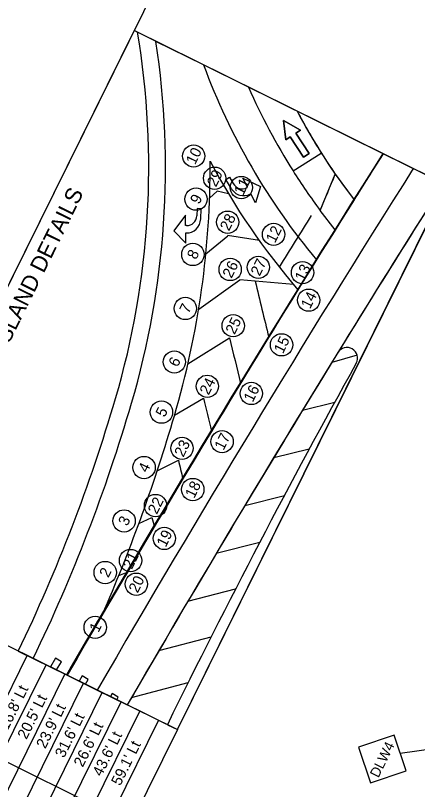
# Model space of a CAD drawing. Extents: x 14097936 to 14128734, y 8632000 to 8683104.
# Drawn here: x 14118361 to 14118650, y 8668139 to 8668694 of the extents above; entities that cross this region are included whole.
import ezdxf

# ---------------------------------------------------------------- set-up
doc = ezdxf.new("R2010")
doc.units = 0
for name, color, linetype in [('Cell', 7, 'Continuous'), ('dsn_stg_shd_prev', 7, 'Continuous'), ('dsnNonPlotable', 7, 'Continuous'), ('dsnPaintPlaceBrokenLaneWhite', 7, 'Continuous'), ('dsnPaintPlaceChannelizingLaneWhite', 7, 'Continuous'), ('dsnPaintPlaceChannelizingLaneYellow', 7, 'Continuous'), ('dsnPaintPlaceStopLineWhite', 7, 'Continuous'), ('dsnShadingPaved', 7, 'Continuous'), ('dsnStdLabel', 7, 'Continuous'), ('dsnStgShadingPrevPav', 7, 'Continuous'), ('dsnStgShadingPropPav', 7, 'Continuous'), ('Level 2', 7, 'Continuous'), ('Level 5', 7, 'Continuous')]:
    doc.layers.add(name, color=color, linetype=linetype)

msp = doc.modelspace()

# ---------------------------------------------------------------- linework, layer by layer
at = {"layer": 'Cell'}
for p, q in [((14118527.19, 8668570.77), (14118527.74, 8668571.09)), ((14118530.15, 8668566.41), (14118529.83, 8668566.23)), ((14118484, 8668543.49), (14118483.38, 8668543.51)), ((14118483.4, 8668538.25), (14118483.77, 8668538.23))]:
    msp.add_line(p, q, dxfattribs=at)
for points in [[(14118515.94, 8668570.32), (14118512.25, 8668576.69), (14118514.83, 8668578.19), (14118517.47, 8668573.64)], [(14118515.94, 8668570.32), (14118512.25, 8668576.69), (14118514.83, 8668578.19), (14118517.47, 8668573.64)], [(14118527.74, 8668571.09), (14118524.36, 8668577.64), (14118537.06, 8668571.63)], [(14118527.74, 8668571.09), (14118524.36, 8668577.64), (14118537.06, 8668571.63)], [(14118527.19, 8668570.77), (14118527.74, 8668571.09)], [(14118537.06, 8668571.63), (14118533.52, 8668559.86), (14118530.15, 8668566.41)], [(14118537.06, 8668571.63), (14118533.52, 8668559.86), (14118530.15, 8668566.41)], [(14118530.15, 8668566.41), (14118529.83, 8668566.23)], [(14118494.19, 8668548.29), (14118494.52, 8668555.65), (14118491.53, 8668555.78), (14118491.3, 8668550.53)], [(14118494.19, 8668548.29), (14118494.52, 8668555.65), (14118491.53, 8668555.78), (14118491.3, 8668550.53)], [(14118483.38, 8668543.51), (14118483.34, 8668550.88), (14118474.86, 8668539.68)], [(14118483.38, 8668543.51), (14118483.34, 8668550.88), (14118474.86, 8668539.68)], [(14118484, 8668543.49), (14118483.38, 8668543.51)], [(14118474.86, 8668539.68), (14118483.44, 8668530.88), (14118483.4, 8668538.25)], [(14118474.86, 8668539.68), (14118483.44, 8668530.88), (14118483.4, 8668538.25)], [(14118483.4, 8668538.25), (14118483.77, 8668538.23)]]:
    msp.add_lwpolyline(points, dxfattribs=at)
for centre, major_axis, start_param, end_param in [((14118523.5, 8668577.14), (-3.69, 6.37), 1.570796, 3.141593), ((14118523.5, 8668577.14), (-3.69, 6.37), 1.570796, 3.141593), ((14118524.56, 8668575.32), (-5.28, 9.09), 1.570796, 3.141593), ((14118524.56, 8668575.32), (-5.28, 9.09), 1.570796, 3.141593), ((14118484.24, 8668548.74), (0.47, 10.5), 3.141593, 4.712389), ((14118484.24, 8668548.74), (0.47, 10.5), 3.141593, 4.712389), ((14118484.33, 8668550.84), (0.33, 7.35), 3.141593, 4.712389), ((14118484.33, 8668550.84), (0.33, 7.35), 3.141593, 4.712389)]:
    msp.add_ellipse(centre, major_axis=major_axis, ratio=0.9474, start_param=start_param, end_param=end_param, dxfattribs=at)
at = {"layer": 'dsn_stg_shd_prev'}
for p, q in [((14118624.96, 8668595.1), (14118448.86, 8668682.17)), ((14118363.35, 8668238.29), (14118398.34, 8668220.99))]:
    msp.add_line(p, q, dxfattribs=at)
msp.add_lwpolyline([(14118398.34, 8668220.99), (14118477.41, 8668181.9), (14118670.56, 8668572.56), (14118624.96, 8668595.1)], dxfattribs=at)
for centre, radius, start, end in [((14117868.92, 8668585.15), 588, 343.63038, 9.49722), ((14127938.79, 8662697.56), 11024, 147.657875, 149.931333), ((14127938.79, 8662697.56), 11024, 147.657875, 149.931333), ((14117293.24, 8668754.25), 1188, 334.25871, 343.63038)]:
    msp.add_arc(centre, radius, start, end, dxfattribs=at)
at = {"layer": 'dsnNonPlotable'}
msp.add_lwpolyline([(14118047.21, 8667875.87), (14118741.94, 8669281.01), (14119647.32, 8668833.36), (14118952.59, 8667428.23)], close=True, dxfattribs=at)
at = {"layer": 'dsnPaintPlaceBrokenLaneWhite'}
msp.add_arc((14127939.53, 8662698.67), 11000, 147.651625, 149.930056, dxfattribs=at)
at = {"layer": 'dsnPaintPlaceChannelizingLaneWhite'}
for p, q in [((14118500.54, 8668563.17), (14118505.96, 8668568.25)), ((14118514.16, 8668566.21), (14118505.96, 8668568.25)), ((14118497.89, 8668523.26), (14118513.54, 8668536.1)), ((14118536.21, 8668532.7), (14118513.46, 8668536.45)), ((14118492.71, 8668483.61), (14118522.19, 8668504.51)), ((14118560.81, 8668501.17), (14118522.19, 8668504.51)), ((14118485.04, 8668444.36), (14118514.86, 8668463.08)), ((14118475.46, 8668407.57), (14118496.28, 8668419.64)), ((14118462.96, 8668367.49), (14118478.14, 8668375.12)), ((14118449.79, 8668329.73), (14118459.21, 8668334.09)), ((14118435.4, 8668292.41), (14118440.17, 8668294.43))]:
    msp.add_line(p, q, dxfattribs=at)
for centre, radius, start, end in [((14118940.85, 8668823), 498, 207.9416, 220.8109), ((14129196.9, 8671052.42), 10964, 193.442919, 193.658396), ((14127939.53, 8662698.67), 11024, 148.263037, 149.677738), ((14129180.95, 8671001.56), 10964, 193.387071, 193.563055), ((14129155.92, 8670985.08), 10964, 193.531964, 193.658396), ((14129135.31, 8670950.8), 10964, 193.586993, 193.658396), ((14129187.85, 8671037.49), 11064, 194.142983, 194.178219), ((14129167.49, 8671003.06), 11064, 194.170915, 194.178219)]:
    msp.add_arc(centre, radius, start, end, dxfattribs=at)
at = {"layer": 'dsnPaintPlaceChannelizingLaneYellow'}
for p, q in [((14118606.33, 8668450.51), (14118588.14, 8668445.33)), ((14118567.26, 8668411.21), (14118590.25, 8668416.79)), ((14118546.51, 8668377.02), (14118572.06, 8668383.31)), ((14118525.88, 8668342.75), (14118554.14, 8668349.83)), ((14118505.37, 8668308.4), (14118536.5, 8668316.32)), ((14118484.99, 8668273.99), (14118519.13, 8668282.8)), ((14118465.08, 8668238.8), (14118501.57, 8668248.36)), ((14118444.6, 8668204.93), (14118485.2, 8668215.72))]:
    msp.add_line(p, q, dxfattribs=at)
for centre, radius, start, end in [((14118599, 8668448.44), 7.62, 330.9739, 148.3847), ((14127971.54, 8662679.38), 11013.37, 148.386532, 149.918423), ((14123657.85, 8665641.26), 5777.9, 150.973912, 153.87509)]:
    msp.add_arc(centre, radius, start, end, dxfattribs=at)
at = {"layer": 'dsnPaintPlaceStopLineWhite'}
msp.add_arc((14127939.53, 8662698.67), 11044, 148.002631, 148.227988, dxfattribs=at)
at = {"layer": 'dsnShadingPaved'}
for p, q in [((14118496.22, 8668658.76), (14118462.06, 8668675.65)), ((14118528.51, 8668642.79), (14118496.22, 8668658.76)), ((14118563.37, 8668625.56), (14118528.51, 8668642.79)), ((14118624.95, 8668595.11), (14118563.37, 8668625.56)), ((14118560.36, 8668582.73), (14118580.65, 8668595.55)), ((14118560.36, 8668582.73), (14118580.65, 8668595.55)), ((14118646.62, 8668584.4), (14118624.8, 8668595.18)), ((14118668.25, 8668573.7), (14118646.62, 8668584.4)), ((14118563.93, 8668497.52), (14118577.22, 8668518.95)), ((14118374.11, 8668232.97), (14118397.88, 8668221.22)), ((14118397.88, 8668221.22), (14118419.98, 8668210.3)), ((14118419.98, 8668210.3), (14118441.54, 8668199.64))]:
    msp.add_line(p, q, dxfattribs=at)
msp.add_lwpolyline([(14118590.62, 8668540.45), (14118579.83, 8668554.37), (14118590.67, 8668580.4), (14118604.14, 8668562.03)], close=True, dxfattribs=at)
for points in [[(14118577.22, 8668518.95), (14118590.62, 8668540.45), (14118579.83, 8668554.37)], [(14118470.24, 8668185.44), (14118477.41, 8668181.9), (14118658.81, 8668548.81)]]:
    msp.add_lwpolyline(points, dxfattribs=at)
for centre, radius, start, end in [((14117868.92, 8668585.15), 600, 343.63038, 8.67481), ((14118940.85, 8668823), 474, 200.2729, 219.9002), ((14118940.85, 8668823), 474, 200.2729, 219.9002), ((14118940.85, 8668823), 450, 203.6065, 212.2703), ((14118940.85, 8668823), 450, 203.6065, 212.2703), ((14118940.85, 8668823), 426, 207.6114, 212.2703), ((14118940.85, 8668823), 426, 207.6114, 217.7768), ((14127783.68, 8662781.45), 10848.25, 147.594047, 149.9045), ((14118940.85, 8668823), 426, 212.2703, 214.7131), ((14126585.99, 8663565), 9417.02, 147.713638, 147.951391), ((14117868.92, 8668585.15), 632, 343.63038, 0.40763), ((14118940.85, 8668823), 498, 207.9416, 220.8109), ((14127939.53, 8662698.67), 11000, 147.651625, 149.930056), ((14127939.53, 8662698.67), 11000, 147.651625, 149.930056), ((14118940.85, 8668823), 450, 212.2703, 216.6514), ((14118940.85, 8668823), 450, 212.2703, 216.6514), ((14115838.27, 8669712.15), 2976, 337.10525, 337.64823), ((14127939.53, 8662698.67), 10976, 147.638369, 149.921821), ((14127939.53, 8662698.67), 10976, 147.75486, 148.384714), ((14118599, 8668448.44), 7.62, 330.9739, 148.3833), ((14123657.85, 8665641.26), 5777.9, 150.973912, 153.875091), ((14117293.24, 8668754.25), 1200, 334.25304, 343.63038), ((14117293.24, 8668754.25), 1232, 336.78135, 343.63038), ((14127783.68, 8662781.45), 10848.25, 149.615198, 149.9045)]:
    msp.add_arc(centre, radius, start, end, dxfattribs=at)
at = {"layer": 'dsnStdLabel'}
for p, q in [((14118163.74, 8667818.25), (14118369.84, 8668235.09)), ((14118177.19, 8667811.6), (14118383.28, 8668228.44)), ((14118190.64, 8667804.96), (14118396.73, 8668221.79)), ((14118220.06, 8668225.47), (14118444.17, 8668114.67)), ((14118204.08, 8667798.31), (14118410.17, 8668215.14)), ((14118217.53, 8667791.66), (14118423.62, 8668208.49)), ((14118230.97, 8667785.01), (14118437.07, 8668201.85)), ((14118244.42, 8667778.36), (14118450.51, 8668195.2)), ((14118257.87, 8667771.72), (14118463.96, 8668188.55)), ((14118637.23, 8668165.11), (14118725.07, 8668177.26))]:
    msp.add_line(p, q, dxfattribs=at)
for points in [[(14118477.41, 8668181.9), (14118670.56, 8668572.56), (14118446.45, 8668683.36), (14118253.3, 8668292.7)], [(14118047.21, 8667875.87), (14118253.3, 8668292.7), (14118477.41, 8668181.9), (14118271.31, 8667765.07)], [(14118615.98, 8668143.67), (14118641.55, 8668152.32), (14118632.9, 8668177.9), (14118607.32, 8668169.25)]]:
    msp.add_lwpolyline(points, close=True, dxfattribs=at)
for centre in [(14118489.11, 8668593.42), (14118489.11, 8668593.42), (14118504.13, 8668577.49), (14118504.13, 8668577.49), (14118523.29, 8668570.81), (14118523.29, 8668570.81), (14118490.81, 8668562.49), (14118490.81, 8668562.49), (14118513.49, 8668545.95), (14118513.49, 8668545.95), (14118546.43, 8668537.21), (14118546.43, 8668537.21), (14118488.55, 8668522.8), (14118488.55, 8668522.8), (14118535.49, 8668513.6), (14118535.49, 8668513.6), (14118515.3, 8668512.03), (14118515.3, 8668512.03), (14118567.19, 8668509.75), (14118567.19, 8668509.75), (14118571.59, 8668490.02), (14118571.59, 8668490.02), (14118483.12, 8668484.06), (14118483.12, 8668484.06), (14118517.47, 8668471.68), (14118517.47, 8668471.68), (14118552.16, 8668457.96), (14118552.16, 8668457.96), (14118475.29, 8668445.68), (14118475.29, 8668445.68), (14118498.9, 8668428.24), (14118498.9, 8668428.24), (14118530.5, 8668423.07), (14118530.5, 8668423.07), (14118466.03, 8668409.69), (14118466.03, 8668409.69), (14118509.49, 8668388.53), (14118509.49, 8668388.53), (14118480.76, 8668383.73), (14118480.76, 8668383.73), (14118453.56, 8668369.93), (14118453.56, 8668369.93), (14118488.5, 8668354.16), (14118488.5, 8668354.16), (14118461.77, 8668342.65), (14118461.77, 8668342.65), (14118439.23, 8668331.63), (14118439.23, 8668331.63), (14118468.07, 8668319.09), (14118468.07, 8668319.09), (14118443.86, 8668303.21), (14118443.86, 8668303.21), (14118425.69, 8668294.59), (14118425.69, 8668294.59), (14118448, 8668286.23), (14118448, 8668286.23), (14118418.53, 8668255.29), (14118418.53, 8668255.29)]:
    msp.add_circle(centre, 8, dxfattribs=at)
at = {"layer": 'dsnStgShadingPrevPav'}
msp.add_lwpolyline([(14118398.42, 8668220.96), (14118477.41, 8668181.9), (14118670.56, 8668572.56), (14118624.99, 8668595.09)], dxfattribs=at)
msp.add_arc((14127939.53, 8662698.67), 11024, 147.664822, 149.938256, dxfattribs=at)
at = {"layer": 'dsnStgShadingPropPav'}
for p, q in [((14118624.96, 8668595.1), (14118448.86, 8668682.17)), ((14118363.35, 8668238.29), (14118398.34, 8668220.99))]:
    msp.add_line(p, q, dxfattribs=at)
for centre, radius, start, end in [((14117868.92, 8668585.15), 588, 343.63038, 9.49722), ((14127938.79, 8662697.56), 11024, 147.657875, 149.931333), ((14117293.24, 8668754.25), 1188, 334.25871, 343.63038)]:
    msp.add_arc(centre, radius, start, end, dxfattribs=at)
at = {"layer": 'Level 2'}
for points in [[(14118567.84, 8668592.49), (14118572.04, 8668595.22), (14118562.49, 8668609.89), (14118565.63, 8668611.93), (14118553.58, 8668619), (14118555.16, 8668605.11), (14118558.3, 8668607.16)], [(14118386.36, 8668226.92), (14118390.85, 8668224.7), (14118394.41, 8668230.66), (14118390.12, 8668233.23)], [(14118406.96, 8668216.73), (14118411.45, 8668214.51), (14118413.44, 8668217.84), (14118409.15, 8668220.4)], [(14118429.44, 8668205.62), (14118433.94, 8668203.39), (14118435.02, 8668205.2), (14118430.73, 8668207.77)]]:
    msp.add_lwpolyline(points, close=True, dxfattribs=at)
at = {"layer": 'Level 5'}
msp.add_lwpolyline([(14118558.3, 8668607.16), (14118555.16, 8668605.11), (14118553.58, 8668619), (14118565.63, 8668611.93), (14118562.49, 8668609.89), (14118572.04, 8668595.22), (14118567.84, 8668592.49), (14118558.3, 8668607.16)], dxfattribs=at)
for points in [[(14118386.36, 8668226.92), (14118390.85, 8668224.7), (14118394.41, 8668230.66), (14118390.12, 8668233.23)], [(14118406.96, 8668216.73), (14118411.45, 8668214.51), (14118413.44, 8668217.84), (14118409.15, 8668220.4)], [(14118429.44, 8668205.62), (14118433.94, 8668203.39), (14118435.02, 8668205.2), (14118430.73, 8668207.77)]]:
    msp.add_lwpolyline(points, close=True, dxfattribs=at)

# ---------------------------------------------------------------- texts
at = {"layer": 'dsnStdLabel'}
for s, height, p in [('10', 7.776, (14118490.09, 8668586.64)), ('29', 7.776, (14118505.11, 8668570.7)), ('11', 7.776, (14118524.59, 8668564.67)), ('PAINTED ISLAND DETAILS', 11.664, (14118322.82, 8668389.94)), ('9', 7.78, (14118493.09, 8668558.34)), ('28', 7.776, (14118514.47, 8668539.16)), ('12', 7.776, (14118547.44, 8668530.49)), ('8', 7.78, (14118490.84, 8668518.65)), ('26', 7.776, (14118516.28, 8668505.24)), ('27', 7.776, (14118536.47, 8668506.81)), ('13', 7.776, (14118568.17, 8668502.96)), ('14', 7.776, (14118572.57, 8668483.24)), ('7', 7.78, (14118485.4, 8668479.91)), ('25', 7.776, (14118518.45, 8668464.89)), ('15', 7.776, (14118553.14, 8668451.17)), ('6', 7.78, (14118477.57, 8668441.52)), ('24', 7.776, (14118499.88, 8668421.46)), ('16', 7.776, (14118531.48, 8668416.28)), ('5', 7.78, (14118468.31, 8668405.53)), ('17', 7.776, (14118510.51, 8668381.8)), ('23', 7.776, (14118481.74, 8668376.94)), ('4', 7.78, (14118455.84, 8668365.78)), ('18', 7.776, (14118489.49, 8668347.37)), ('22', 7.776, (14118462.75, 8668335.87)), ('3', 7.78, (14118441.51, 8668327.47)), ('19', 7.776, (14118469.05, 8668312.3)), ('21', 7.776, (14118444.84, 8668296.43)), ('2', 7.78, (14118427.97, 8668290.43)), ('20', 7.776, (14118448.98, 8668279.44)), ('1', 7.78, (14118420.81, 8668251.14)), ("16.8' Lt", 7.776, (14118355.82, 8668181.04)), ("20.5' Lt", 7.776, (14118369.27, 8668174.39)), ("23.9' Lt", 7.776, (14118382.71, 8668167.75)), ("31.6' Lt", 7.776, (14118396.16, 8668161.1)), ("26.6' Lt", 7.776, (14118409.6, 8668154.45)), ("43.6' Lt", 7.776, (14118423.05, 8668147.8)), ("59.1' Lt", 7.776, (14118436.5, 8668141.15)), ('DLW4', 7.2, (14118621.58, 8668146.88))]:
    msp.add_text(s, height=height, rotation=63.6912, dxfattribs=at).set_placement(p)

doc.saveas('drawing.dxf')
